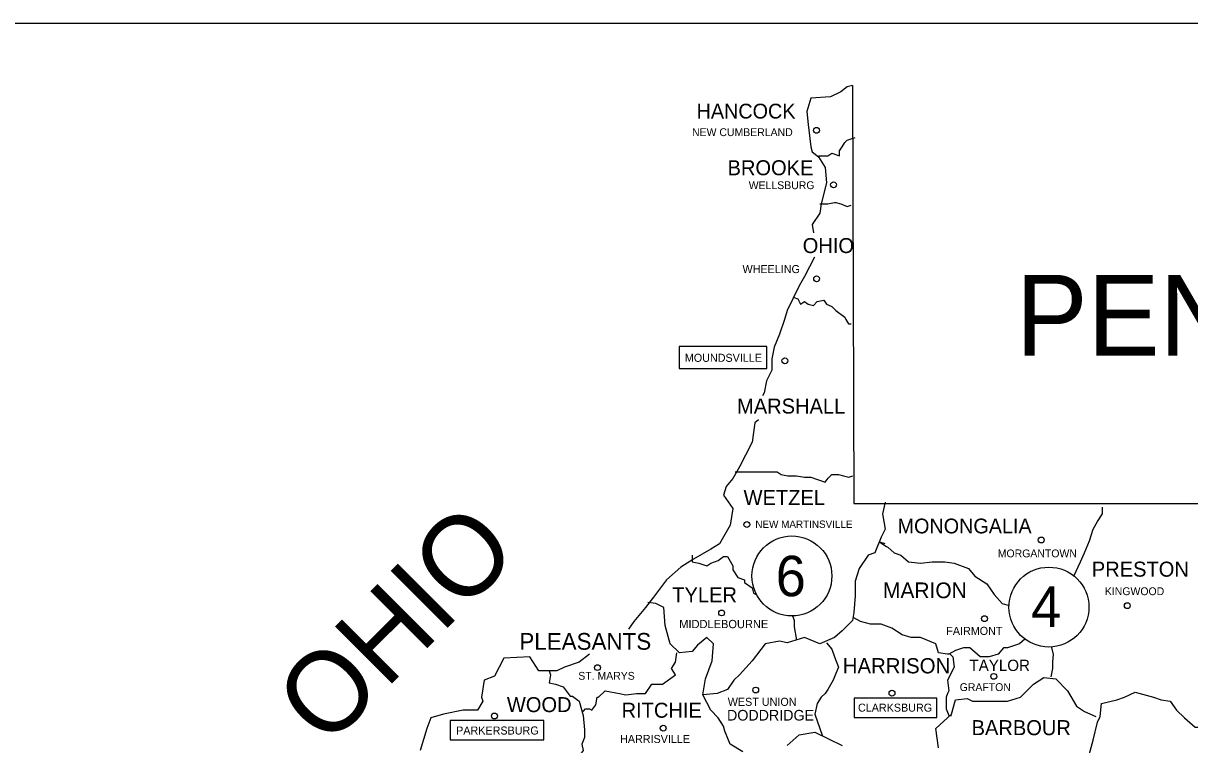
# Model space of a CAD drawing. Extents: x -2.1 to 5.9, y -23.5 to -12.8.
# Drawn here: x 2.655 to 4.174, y -21.85 to -20.91 of the extents above; entities that cross this region are included whole.
import ezdxf

# ---------------------------------------------------------------- set-up
doc = ezdxf.new("R2010")
doc.units = 0
doc.layers.add('Construction Line', color=7, linetype='Continuous')

msp = doc.modelspace()

# ---------------------------------------------------------------- linework, layer by layer
at = {"layer": 'Construction Line'}
msp.add_line((5.62, -20.9101), (-1.8802, -20.9101), dxfattribs=at)
for points in [[(3.7346, -20.991), (3.7278, -20.9927), (3.7193, -20.9992), (3.706, -21.006), (3.6802, -21.0077), (3.6751, -21.025), (3.6768, -21.0417), (3.6802, -21.0709), (3.6819, -21.0777), (3.6904, -21.0842), (3.6989, -21.0978), (3.7006, -21.1179), (3.6938, -21.1454), (3.6921, -21.1573), (3.6819, -21.1723), (3.6836, -21.1831)], [(3.7346, -20.991), (3.7363, -21.5355), (4.206, -21.5355), (4.206, -21.8304)], [(3.6904, -21.0828), (3.7023, -21.0828), (3.7077, -21.0791), (3.7176, -21.0828), (3.7176, -21.076), (3.7213, -21.0709), (3.7244, -21.0655), (3.7278, -21.0621), (3.738, -21.0587)], [(3.6921, -21.1454), (3.7023, -21.1454), (3.7111, -21.1437), (3.7128, -21.1437), (3.7193, -21.1454), (3.7278, -21.1488), (3.7329, -21.1471)], [(3.685, -21.2148), (3.672, -21.24), (3.6652, -21.2522), (3.6567, -21.2692), (3.6496, -21.2842), (3.6462, -21.2961), (3.6394, -21.3151), (3.6326, -21.3318), (3.6295, -21.3471), (3.6295, -21.3621), (3.6227, -21.376), (3.6193, -21.3913), (3.6173, -21.3956)], [(3.6584, -21.2675), (3.6635, -21.2692), (3.6669, -21.276), (3.672, -21.2726), (3.6768, -21.276), (3.6836, -21.2777), (3.6887, -21.2726), (3.6972, -21.2709), (3.7006, -21.276), (3.7077, -21.2791), (3.7128, -21.2842), (3.7244, -21.2927), (3.7261, -21.2961), (3.7295, -21.3015), (3.7329, -21.3015)], [(3.6122, -21.4267), (3.6074, -21.4304), (3.604, -21.4556), (3.5952, -21.4729), (3.5873, -21.4879), (3.5785, -21.5032), (3.57, -21.5134), (3.5666, -21.525), (3.5785, -21.5423), (3.5751, -21.5641), (3.5615, -21.5882), (3.5499, -21.595), (3.5275, -21.6083), (3.5108, -21.6185), (3.4921, -21.6352), (3.4754, -21.6576), (3.4649, -21.6712), (3.4496, -21.6896), (3.4428, -21.6993)], [(3.5819, -21.4944), (3.6363, -21.4944), (3.6417, -21.4978), (3.6502, -21.4995), (3.6618, -21.4995), (3.672, -21.5012), (3.6771, -21.5012), (3.6788, -21.5012), (3.6805, -21.5012), (3.6989, -21.5078), (3.7029, -21.5027), (3.7043, -21.5012), (3.7077, -21.4978), (3.7162, -21.4978), (3.723, -21.4995), (3.7298, -21.5012), (3.7349, -21.4995)], [(3.7771, -21.5338), (3.7737, -21.5491), (3.7771, -21.5692), (3.772, -21.5794), (3.7638, -21.5998), (3.755, -21.6032), (3.7431, -21.6202), (3.738, -21.6369), (3.738, -21.6559), (3.7363, -21.6777), (3.7346, -21.6879), (3.7213, -21.7015), (3.7111, -21.7103), (3.6921, -21.7185), (3.672, -21.7103), (3.6496, -21.7171), (3.6394, -21.7151), (3.621, -21.7185), (3.604, -21.7406), (3.5873, -21.759), (3.5802, -21.7658), (3.5717, -21.778), (3.5581, -21.7831), (3.5397, -21.7848)], [(4.0224, -21.6307), (4.023, -21.6304), (4.0315, -21.6117), (4.0366, -21.5998), (4.0431, -21.5845), (4.0482, -21.5692), (4.0536, -21.559), (4.0604, -21.5491), (4.0604, -21.5406)], [(3.7771, -21.5882), (3.7703, -21.5862), (3.7788, -21.5916), (3.7805, -21.5927), (3.789, -21.5998), (3.7975, -21.6032), (3.8074, -21.6117), (3.823, -21.6134), (3.8383, -21.6117), (3.855, -21.6117), (3.8669, -21.6134), (3.8856, -21.6202), (3.8941, -21.6304), (3.9094, -21.6403), (3.9193, -21.6542), (3.9295, -21.6661), (3.9386, -21.6687)], [(3.5258, -21.6032), (3.5258, -21.6117), (3.5346, -21.6134), (3.5448, -21.6168), (3.5499, -21.6134), (3.5598, -21.61), (3.5666, -21.6049), (3.5717, -21.6049), (3.5785, -21.6168), (3.5785, -21.6219), (3.5853, -21.6321), (3.5941, -21.6352), (3.5941, -21.6386), (3.604, -21.6454), (3.6057, -21.6525), (3.6091, -21.6542)], [(3.5918, -21.8593), (3.5751, -21.8491), (3.5683, -21.8324), (3.5666, -21.8256), (3.5598, -21.8151), (3.5499, -21.8049), (3.5397, -21.7848), (3.5431, -21.7641), (3.5516, -21.7406), (3.5533, -21.7185), (3.5448, -21.7103), (3.5326, -21.7202), (3.5258, -21.7287), (3.5091, -21.7304), (3.4972, -21.7185), (3.4904, -21.6947), (3.4887, -21.6712), (3.4782, -21.6661), (3.468, -21.6647)], [(3.6559, -21.6823), (3.6567, -21.6828), (3.6584, -21.6879), (3.6584, -21.6964), (3.6618, -21.7137)], [(3.959, -21.7126), (3.9519, -21.7185), (3.9366, -21.7236), (3.9312, -21.7236), (3.9244, -21.7321), (3.9128, -21.7355), (3.9009, -21.7355), (3.8873, -21.7236), (3.8791, -21.7236), (3.8686, -21.727), (3.8601, -21.7321), (3.8584, -21.7321), (3.8468, -21.7304), (3.8431, -21.7185), (3.823, -21.7103), (3.8108, -21.7103), (3.7992, -21.7069), (3.7856, -21.6981), (3.772, -21.693), (3.7581, -21.693), (3.7448, -21.6896), (3.7363, -21.6845)], [(3.7006, -21.7171), (3.7077, -21.7253), (3.7111, -21.7355), (3.7162, -21.7491), (3.7128, -21.7573), (3.7094, -21.7658), (3.7023, -21.778), (3.6989, -21.7831), (3.6938, -21.7882), (3.6887, -21.7964), (3.6853, -21.81), (3.6921, -21.829), (3.6955, -21.8389)], [(3.9938, -21.7231), (3.9938, -21.7233), (3.9961, -21.7324), (3.995, -21.742), (3.995, -21.7505), (3.993, -21.7613)], [(3.3918, -21.7321), (3.3785, -21.7423), (3.3595, -21.7491), (3.3496, -21.7539), (3.3258, -21.7539), (3.3142, -21.7355), (3.2802, -21.7372), (3.2683, -21.7607), (3.2547, -21.7658), (3.2513, -21.7882), (3.253, -21.7933), (3.2459, -21.8049), (3.2275, -21.8049), (3.202, -21.81), (3.1853, -21.8151), (3.1799, -21.829), (3.1714, -21.8576)], [(3.3836, -21.8066), (3.387, -21.8032), (3.3921, -21.8032), (3.3952, -21.8049), (3.4003, -21.7981), (3.402, -21.7882), (3.4037, -21.7882), (3.4122, -21.7797), (3.4312, -21.7831), (3.4394, -21.7848), (3.453, -21.7831), (3.4649, -21.7831), (3.4731, -21.7712), (3.487, -21.7712), (3.504, -21.759), (3.4989, -21.7508), (3.504, -21.7423), (3.5057, -21.7304)], [(3.8612, -21.7316), (3.8652, -21.7355), (3.8669, -21.7491), (3.8584, -21.7658), (3.8601, -21.7797), (3.8584, -21.7831), (3.8567, -21.7882), (3.8567, -21.795), (3.8567, -21.8032), (3.8601, -21.8117), (3.8635, -21.8117)], [(3.3394, -21.7539), (3.3411, -21.759), (3.3394, -21.7695), (3.3479, -21.7712), (3.3578, -21.7746), (3.3666, -21.7865), (3.37, -21.7865), (3.3785, -21.7933), (3.3836, -21.8117), (3.3853, -21.8304), (3.3853, -21.8406), (3.3819, -21.8491), (3.3836, -21.8576), (3.3785, -21.8644), (3.37, -21.8743), (3.3612, -21.8743), (3.353, -21.876), (3.3496, -21.8811)], [(3.8468, -21.8542), (3.8431, -21.829), (3.8635, -21.81), (3.8686, -21.7913), (3.8839, -21.7899), (3.8907, -21.7933), (3.9094, -21.7933), (3.9366, -21.7933), (3.9536, -21.7882), (3.9703, -21.7712), (3.9839, -21.7624), (3.9995, -21.7641), (4.0145, -21.7797), (4.0264, -21.7998), (4.0366, -21.8066), (4.0516, -21.8134)], [(4.0315, -21.8967), (4.0332, -21.8848), (4.0417, -21.8678), (4.0482, -21.844), (4.0536, -21.8205), (4.057, -21.8134), (4.0587, -21.7964), (4.0788, -21.7913), (4.089, -21.7882), (4.1026, -21.7814), (4.1267, -21.7882), (4.1366, -21.7913), (4.1485, -21.7933), (4.1567, -21.8049), (4.1669, -21.8151), (4.1808, -21.8273), (4.2029, -21.8273)], [(3.6496, -21.8508), (3.6652, -21.8372), (3.6853, -21.8338), (3.7213, -21.8508)]]:
    msp.add_lwpolyline(points, dxfattribs=at)
for points in [[(3.5088, -21.3313), (3.5088, -21.3596), (3.623, -21.3596), (3.623, -21.3313)], [(3.7369, -21.7894), (3.7369, -21.8146), (3.8445, -21.8146), (3.8445, -21.7894)], [(3.2105, -21.8185), (3.2105, -21.8438), (3.3326, -21.8438), (3.3326, -21.8185)]]:
    msp.add_lwpolyline(points, close=True, dxfattribs=at)
for centre, radius in [((3.6877, -21.0495), 0.00381), ((3.7099, -21.1204), 0.00381), ((3.6878, -21.2429), 0.00381), ((3.6465, -21.3497), 0.00381), ((3.5969, -21.5631), 0.00381), ((3.6556, -21.6301), 0.0521), ((3.9804, -21.5832), 0.00381), ((3.9904, -21.6707), 0.0521), ((3.5641, -21.6783), 0.00381), ((4.0925, -21.6688), 0.00381), ((3.9065, -21.6857), 0.00381), ((3.4024, -21.7495), 0.00381), ((3.9186, -21.7609), 0.00381), ((3.6085, -21.7787), 0.00381), ((3.786, -21.7829), 0.00381), ((3.2682, -21.8125), 0.00381), ((3.488, -21.8284), 0.00381)]:
    msp.add_circle(centre, radius, dxfattribs=at)

# ---------------------------------------------------------------- texts
for s, height, p in [('HANCOCK', 0.01926, (3.5315, -21.0341)), ('NEW CUMBERLAND', 0.010199, (3.5256, -21.057)), ('BROOKE', 0.01955, (3.5718, -21.108)), ('WELLSBURG', 0.0102, (3.5994, -21.1261)), ('OHIO', 0.01955, (3.6697, -21.2094)), ('WHEELING', 0.01048, (3.5913, -21.2355)), ('PENNSYLVANIA', 0.105101, (3.9471, -21.3429)), ('MOUNDSVILLE', 0.010481, (3.5162, -21.3511)), ('MARSHALL', 0.01955, (3.5842, -21.4185)), ('WETZEL', 0.01955, (3.5927, -21.5378)), ('NEW MARTINSVILLE', 0.009631, (3.608, -21.5675)), ('MONONGALIA', 0.01926, (3.7933, -21.5746)), ('6', 0.0527, (3.6346, -21.6565)), ('MORGANTOWN', 0.0102, (3.9238, -21.6058)), ('PRESTON', 0.01955, (4.0463, -21.631)), ('TYLER', 0.01955, (3.4998, -21.6644)), ('MARION', 0.0204, (3.7743, -21.659)), ('4', 0.0527, (3.9673, -21.6964)), ('KINGWOOD', 0.0102, (4.0633, -21.6551)), ('MIDDLEBOURNE', 0.010765, (3.5089, -21.6981)), ('PLEASANTS', 0.02181, (3.3006, -21.7262)), ('FAIRMONT', 0.01048, (3.8567, -21.7069)), ('HARRISON', 0.01983, (3.7219, -21.757)), ('TAYLOR', 0.01473, (3.8869, -21.7539)), ('ST. MARYS', 0.0102, (3.3774, -21.7653)), ('GRAFTON', 0.0102, (3.8742, -21.78)), ('WOOD', 0.01955, (3.2844, -21.8075)), ('RITCHIE', 0.01955, (3.4338, -21.8148)), ('WEST UNION', 0.01048, (3.5721, -21.7993)), ('CLARKSBURG', 0.01048, (3.7417, -21.8069)), ('DODDRIDGE', 0.01388, (3.5711, -21.8185)), ('PARKERSBURG', 0.010481, (3.2183, -21.8367)), ('BARBOUR', 0.01955, (3.8897, -21.8375)), ('HARRISVILLE', 0.010481, (3.4318, -21.8477))]:
    msp.add_text(s, height=height, dxfattribs=at).set_placement(p)
msp.add_text('OHIO', height=0.10497, rotation=45, dxfattribs=at).set_placement((3.0493, -21.8556))

doc.saveas('drawing.dxf')
